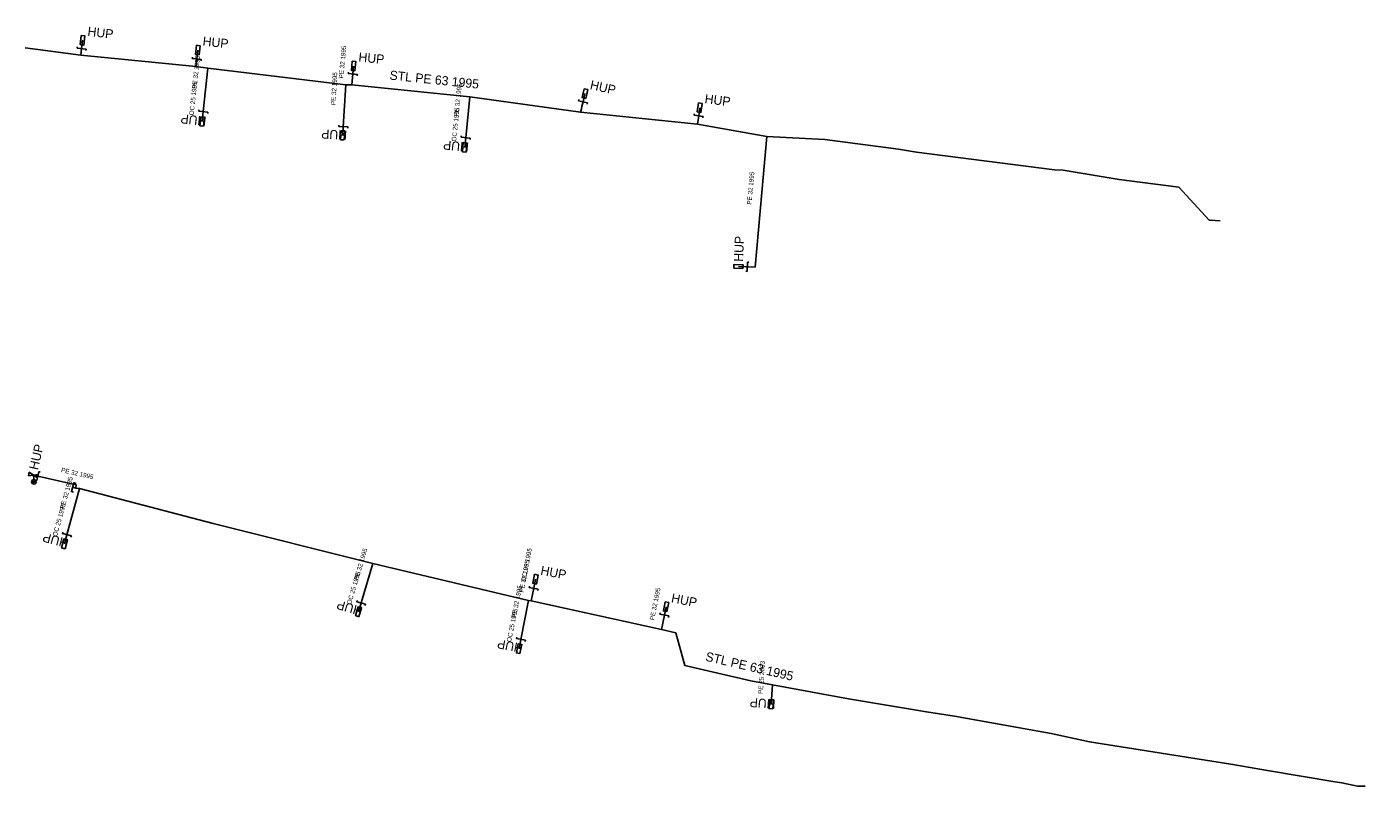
# Model space of a CAD drawing. Extents: x -745298 to -745026, y -1052719 to -1052281.
# Drawn here: x -745172.2 to -745025.7, y -1052432.7 to -1052349.5 of the extents above; entities that cross this region are included whole.
import ezdxf

# ---------------------------------------------------------------- set-up
doc = ezdxf.new("R2010")
doc.units = 0
for name, color, linetype in [('ST Úsek p_ípojky - provoz', 7, 'Continuous'), ('ST Úsek plynovodu - provoz', 7, 'Continuous'), ('ST_HUP_22_23_popis', 7, 'Continuous'), ('ST_HUP_24_popis', 7, 'Continuous'), ('Vrstva 1', 7, 'Continuous')]:
    doc.layers.add(name, color=color, linetype=linetype)

msp = doc.modelspace()

# ---------------------------------------------------------------- linework, layer by layer
at = {"layer": 'ST Úsek p_ípojky - provoz'}
for points in [[(-745166.17, -1052351.88), (-745166.06, -1052350.96)], [(-745166.25, -1052352.58), (-745166.17, -1052351.88)], [(-745153.57, -1052353), (-745153.46, -1052352.03)], [(-745153.66, -1052353.83), (-745153.57, -1052353)], [(-745152.34, -1052354), (-745152.85, -1052358.77)], [(-745136.48, -1052354.65), (-745136.4, -1052353.78)], [(-745136.59, -1052355.84), (-745136.48, -1052354.65)], [(-745137.26, -1052355.84), (-745137.53, -1052360.42)], [(-745111.29, -1052357.7), (-745111.09, -1052356.79)], [(-745123.69, -1052357.17), (-745124.13, -1052361.63)], [(-745111.55, -1052358.83), (-745111.47, -1052358.46)], [(-745111.47, -1052358.46), (-745111.41, -1052358.21)], [(-745111.41, -1052358.21), (-745111.29, -1052357.7)], [(-745098.63, -1052359.24), (-745098.52, -1052358.34)], [(-745152.85, -1052358.77), (-745152.97, -1052359.85)], [(-745098.75, -1052360.16), (-745098.63, -1052359.24)], [(-745137.53, -1052360.42), (-745137.59, -1052361.37)], [(-745091.19, -1052361.49), (-745092.46, -1052375.8), (-745093.31, -1052375.77)], [(-745124.13, -1052361.63), (-745124.24, -1052362.69)], [(-745093.31, -1052375.77), (-745094.28, -1052375.73)], [(-745170.95, -1052398.69), (-745171.45, -1052398.58)], [(-745166.8, -1052400), (-745166.75, -1052399.65), (-745170.95, -1052398.69)], [(-745166.41, -1052400.06), (-745167.77, -1052405.11)], [(-745167.77, -1052405.11), (-745168.04, -1052406.11)], [(-745134.3, -1052408.27), (-745135.58, -1052412.58)], [(-745116.95, -1052412.36), (-745116.69, -1052410.98)], [(-745116.69, -1052410.98), (-745116.5, -1052409.98)], [(-745135.58, -1052412.58), (-745135.86, -1052413.55)], [(-745117.24, -1052412.31), (-745118.08, -1052416.57)], [(-745102.7, -1052415.5), (-745102.38, -1052413.91)], [(-745102.38, -1052413.91), (-745102.2, -1052413)], [(-745118.08, -1052416.57), (-745118.29, -1052417.6)], [(-745090.55, -1052421.57), (-745090.69, -1052423.68)]]:
    msp.add_lwpolyline(points, dxfattribs=at)
at = {"layer": 'ST Úsek plynovodu - provoz'}
for points in [[(-745172.36, -1052351.77), (-745166.25, -1052352.58), (-745153.66, -1052353.83), (-745152.34, -1052354), (-745137.26, -1052355.84), (-745136.59, -1052355.84), (-745123.69, -1052357.17), (-745111.55, -1052358.83), (-745098.75, -1052360.16), (-745091.19, -1052361.49), (-745084.83, -1052361.83), (-745076.78, -1052362.89), (-745074.8, -1052363.22), (-745059.7, -1052365.14), (-745058.74, -1052365.18), (-745052.61, -1052366.19), (-745046.07, -1052367.04), (-745042.77, -1052370.65), (-745042.64, -1052370.66), (-745041.54, -1052370.75)], [(-745167.15, -1052399.9), (-745166.8, -1052400), (-745166.41, -1052400.06), (-745151.77, -1052403.89), (-745134.3, -1052408.27), (-745117.24, -1052412.31), (-745116.95, -1052412.36), (-745102.7, -1052415.5), (-745101.13, -1052415.86), (-745100.16, -1052419.42), (-745092.92, -1052421.1), (-745090.55, -1052421.57), (-745082.25, -1052423.07), (-745073.71, -1052424.51), (-745070.64, -1052425), (-745060.07, -1052426.87), (-745055.85, -1052427.81), (-745040.39, -1052430.24), (-745036.38, -1052430.95), (-745029.01, -1052432.17), (-745028.23, -1052432.27), (-745026.54, -1052432.64), (-745026.12, -1052432.66), (-745025.68, -1052432.66)]]:
    msp.add_lwpolyline(points, dxfattribs=at)
at = {"layer": 'Vrstva 1'}
for p, q in [((-745166.66, -1052351.82), (-745166.65, -1052351.67)), ((-745165.67, -1052351.94), (-745166.66, -1052351.82)), ((-745165.67, -1052351.94), (-745165.69, -1052352.09)), ((-745154.06, -1052352.94), (-745154.05, -1052352.79)), ((-745153.07, -1052353.05), (-745154.06, -1052352.94)), ((-745153.07, -1052353.05), (-745153.09, -1052353.2)), ((-745136.98, -1052354.61), (-745136.97, -1052354.46)), ((-745135.98, -1052354.7), (-745136.98, -1052354.61)), ((-745135.98, -1052354.7), (-745136, -1052354.85)), ((-745111.78, -1052357.59), (-745111.75, -1052357.44)), ((-745110.81, -1052357.81), (-745111.78, -1052357.59)), ((-745110.81, -1052357.81), (-745110.84, -1052357.96)), ((-745153.35, -1052358.72), (-745153.33, -1052358.57)), ((-745152.36, -1052358.82), (-745153.35, -1052358.72)), ((-745152.36, -1052358.82), (-745152.37, -1052358.97)), ((-745099.13, -1052359.17), (-745099.11, -1052359.02)), ((-745098.14, -1052359.3), (-745099.13, -1052359.17)), ((-745098.14, -1052359.3), (-745098.16, -1052359.45)), ((-745138.03, -1052360.39), (-745138.02, -1052360.24)), ((-745138.03, -1052360.39), (-745137.03, -1052360.45)), ((-745137.03, -1052360.45), (-745137.04, -1052360.6)), ((-745124.63, -1052361.58), (-745124.62, -1052361.43)), ((-745124.63, -1052361.58), (-745123.64, -1052361.68)), ((-745123.64, -1052361.68), (-745123.65, -1052361.83)), ((-745093.32, -1052376.27), (-745093.3, -1052375.27)), ((-745093.3, -1052375.27), (-745093.15, -1052375.27)), ((-745093.32, -1052376.27), (-745093.47, -1052376.26)), ((-745171.45, -1052398.57), (-745171.41, -1052399.07)), ((-745171.06, -1052399.18), (-745171.2, -1052399.15)), ((-745170.84, -1052398.21), (-745171.06, -1052399.18)), ((-745170.84, -1052398.21), (-745170.69, -1052398.24)), ((-745168.25, -1052404.98), (-745168.21, -1052404.84)), ((-745168.25, -1052404.98), (-745167.29, -1052405.24)), ((-745167.29, -1052405.24), (-745167.33, -1052405.39)), ((-745117.18, -1052410.88), (-745117.15, -1052410.73)), ((-745116.2, -1052411.07), (-745117.18, -1052410.88)), ((-745116.2, -1052411.07), (-745116.22, -1052411.22)), ((-745136.06, -1052412.45), (-745136.01, -1052412.3)), ((-745135.09, -1052412.72), (-745136.06, -1052412.45)), ((-745135.09, -1052412.72), (-745135.14, -1052412.87)), ((-745102.87, -1052413.82), (-745102.84, -1052413.67)), ((-745101.89, -1052414.01), (-745102.87, -1052413.82)), ((-745101.89, -1052414.01), (-745101.92, -1052414.16)), ((-745118.57, -1052416.47), (-745118.55, -1052416.33)), ((-745117.59, -1052416.67), (-745118.57, -1052416.47)), ((-745117.59, -1052416.67), (-745117.62, -1052416.81))]:
    msp.add_line(p, q, dxfattribs=at)
for points in [[(-745166.2, -1052350.44), (-745165.8, -1052350.48), (-745165.92, -1052351.48), (-745166.32, -1052351.43)], [(-745153.6, -1052351.51), (-745153.21, -1052351.55), (-745153.32, -1052352.55), (-745153.71, -1052352.5)], [(-745136.55, -1052353.26), (-745136.15, -1052353.3), (-745136.25, -1052354.3), (-745136.64, -1052354.26)], [(-745111.17, -1052356.26), (-745110.78, -1052356.35), (-745111, -1052357.32), (-745111.39, -1052357.23)], [(-745098.66, -1052357.82), (-745098.26, -1052357.87), (-745098.38, -1052358.86), (-745098.78, -1052358.81)], [(-745152.83, -1052360.37), (-745153.22, -1052360.32), (-745153.11, -1052359.33), (-745152.72, -1052359.37)], [(-745137.42, -1052361.88), (-745137.82, -1052361.86), (-745137.76, -1052360.86), (-745137.36, -1052360.88)], [(-745124.09, -1052363.21), (-745124.49, -1052363.17), (-745124.39, -1052362.17), (-745123.99, -1052362.21)], [(-745094.78, -1052375.91), (-745094.77, -1052375.51), (-745093.77, -1052375.55), (-745093.79, -1052375.95)], [(-745167.98, -1052406.64), (-745168.36, -1052406.54), (-745168.1, -1052405.57), (-745167.72, -1052405.68)], [(-745116.6, -1052409.45), (-745116.21, -1052409.53), (-745116.4, -1052410.51), (-745116.79, -1052410.43)], [(-745102.3, -1052412.47), (-745101.91, -1052412.55), (-745102.1, -1052413.53), (-745102.49, -1052413.45)], [(-745135.81, -1052414.09), (-745136.19, -1052413.97), (-745135.91, -1052413.01), (-745135.53, -1052413.13)], [(-745118.19, -1052418.13), (-745118.58, -1052418.05), (-745118.39, -1052417.07), (-745118, -1052417.15)], [(-745090.52, -1052424.19), (-745090.92, -1052424.16), (-745090.85, -1052423.17), (-745090.45, -1052423.19)]]:
    msp.add_lwpolyline(points, close=True, dxfattribs=at)
for points in [[(-745171.98, -1052398.66), (-745171.89, -1052398.27), (-745171.01, -1052398.89), (-745170.92, -1052398.5), (-745171.98, -1052398.66)], [(-745167.05, -1052400.45), (-745167.29, -1052400.38), (-745167.01, -1052399.42), (-745166.77, -1052399.49)]]:
    msp.add_lwpolyline(points, dxfattribs=at)
for centre, radius in [((-745171.39, -1052399.32), 0.249), ((-745171.49, -1052399.32), 0.0614), ((-745171.29, -1052399.3), 0.0614)]:
    msp.add_circle(centre, radius, dxfattribs=at)

# ---------------------------------------------------------------- texts
at = {"layer": 'ST Úsek p_ípojky - provoz'}
for s, rotation, p in [('PE 32 1995', 84.749, (-745137.53, -1052355.16)), ('PE 32 1995', 83.8629, (-745153.59, -1052356.28)), ('OC 25 1995', 83.8, (-745153.91, -1052359.2)), ('PE 32 1995', 86.5918, (-745138.39, -1052358.07)), ('PE 32 1995', 84.3314, (-745124.91, -1052359.3)), ('OC 25 1995', 84.3701, (-745125.18, -1052362.06)), ('PE 32 1995', 84.9283, (-745092.86, -1052368.98)), ('PE 32 1995', 347.168, (-745168.45, -1052398.24)), ('PE 32 1995', 74.9283, (-745168.06, -1052402.33)), ('OC 25 1995', 74.9253, (-745168.87, -1052405.35)), ('PE 32 1995', 73.5386, (-745135.9, -1052410.14)), ('OC 25 1995', 79.2554, (-745117.58, -1052410.29)), ('PE 32 1995', 79.288, (-745117.8, -1052411.48)), ('OC 25 1995', 73.6394, (-745136.68, -1052412.79)), ('PE 32 1995', 78.7936, (-745118.64, -1052414.25)), ('PE 32 1995', 78.6276, (-745103.52, -1052414.51)), ('OC 25 1995', 78.7329, (-745119.17, -1052416.89)), ('PE 25 2003', 86.2292, (-745091.62, -1052422.56))]:
    msp.add_text(s, height=0.5, rotation=rotation, dxfattribs=at).set_placement(p)
at = {"layer": 'ST Úsek plynovodu - provoz'}
for rotation, p in [(354.1136, (-745132.5, -1052355.26)), (346.936, (-745097.96, -1052418.9))]:
    msp.add_text('STL PE 63 1995', height=1, rotation=rotation, dxfattribs=at).set_placement(p)
at = {"layer": 'ST_HUP_22_23_popis'}
for rotation, p in [(353.26, (-745165.56, -1052350.46)), (353.66, (-745152.96, -1052351.53)), (354.51, (-745135.9, -1052353.28)), (347.22, (-745110.59, -1052356.29)), (352.84, (-745098.02, -1052357.84)), (173.8, (-745152.47, -1052359.35)), (176.73, (-745137.09, -1052360.87)), (174.37, (-745123.74, -1052362.19)), (87.74, (-745093.78, -1052375.23)), (164.93, (-745167.54, -1052405.61)), (349.26, (-745116, -1052409.48)), (163.64, (-745135.36, -1052413.05)), (348.81, (-745101.7, -1052412.5)), (168.73, (-745117.79, -1052417.1)), (176, (-745090.19, -1052423.18))]:
    msp.add_text('HUP', height=1, rotation=rotation, dxfattribs=at).set_placement(p)
at = {"layer": 'ST_HUP_24_popis'}
msp.add_text('HUP', height=1, rotation=77.1, dxfattribs=at).set_placement((-745170.95, -1052398.08))

doc.saveas('drawing.dxf')
